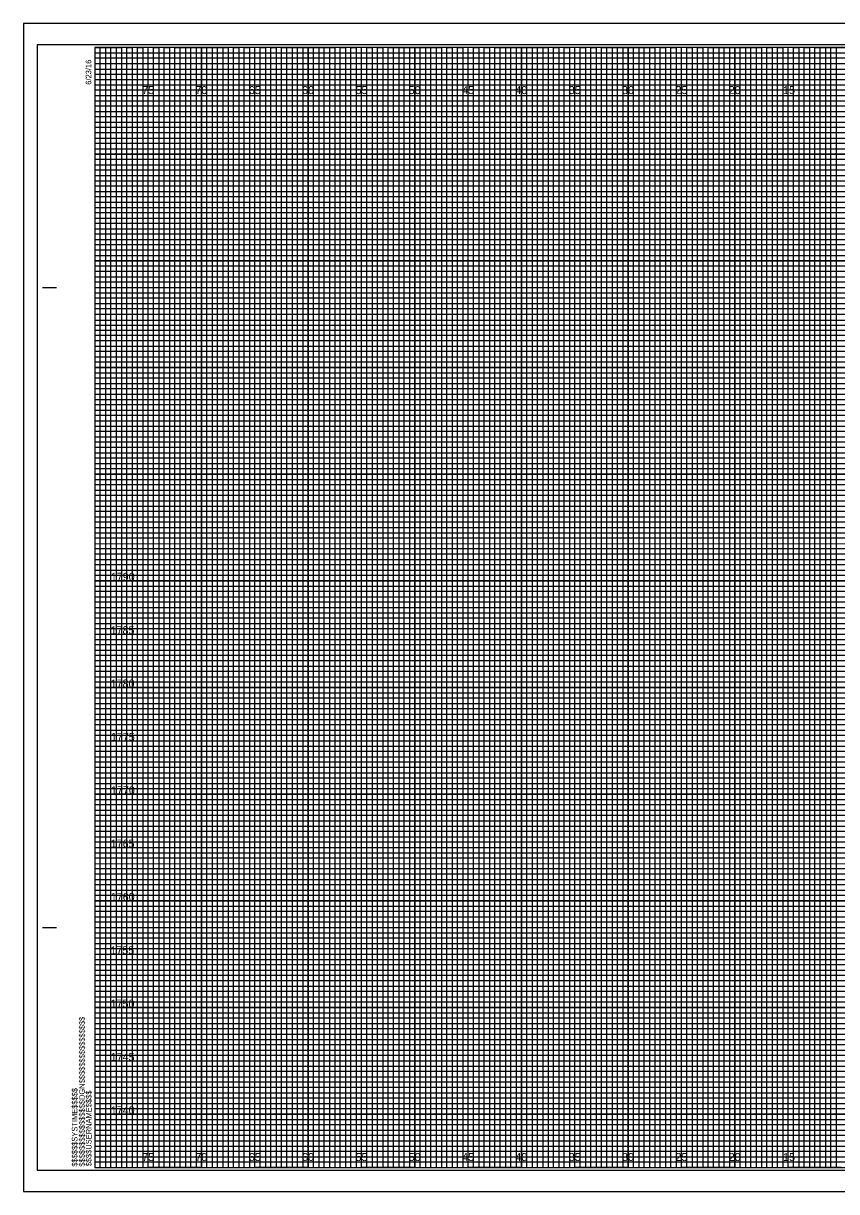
# Model space of a CAD drawing. Extents: x -7 to 162, y -2 to 217.
# Drawn here: x -6.7 to 69.5, y 107.7 to 217.2 of the extents above; entities that cross this region are included whole.
import ezdxf

# ---------------------------------------------------------------- set-up
doc = ezdxf.new("R2010")
doc.units = 0
for name, color, linetype in [('Raster_Level_0', 7, 'Continuous'), ('Scratch_Level_3', 7, 'Continuous'), ('Sheet Cross Section CELL', 7, 'Continuous'), ('Sheet Cross Section Grid Major CELL', 7, 'Continuous'), ('Sheet Cross Section Grid Middle CELL', 7, 'Continuous'), ('Sheet Cross Section Grid Minor 1 CELL', 7, 'Continuous'), ('Sheet Cross Section Grid Minor 2 CELL', 7, 'Continuous'), ('Sheet Cutting Line CELL', 7, 'Continuous'), ('Sheet DOT Grid CELL', 7, 'Continuous'), ('Sheet Plot Border Inside CELL', 7, 'Continuous'), ('Sheet Plot Border Outside CELL', 7, 'Continuous')]:
    doc.layers.add(name, color=color, linetype=linetype)

msp = doc.modelspace()

# ---------------------------------------------------------------- linework, layer by layer
at = {"layer": 'Sheet Cross Section CELL'}
for p, q in [((-4.9, 192.5), (-3.65, 192.5)), ((-4.85, 192.5), (-3.6, 192.5)), ((-4.9, 132.5), (-3.65, 132.5)), ((-4.85, 132.5), (-3.6, 132.5)), ((0, 110), (0, 110)), ((0, 110), (0, 110)), ((0, 110), (0, 110)), ((0, 110), (0, 110)), ((0, 110), (0, 110)), ((0, 110), (0, 110)), ((0, 110), (0, 110))]:
    msp.add_line(p, q, dxfattribs=at)
msp.add_lwpolyline([(160, 215), (0, 215), (0, 110), (160, 110)], close=True, dxfattribs=at)
at = {"layer": 'Sheet Cross Section Grid Major CELL'}
for p, q in [((5, 215), (0, 215)), ((5, 110), (5, 215)), ((15, 215), (10, 215)), ((10, 215), (10, 110)), ((15, 110), (15, 215)), ((25, 215), (20, 215)), ((20, 215), (20, 110)), ((25, 110), (25, 215)), ((35, 215), (30, 215)), ((30, 215), (30, 110)), ((35, 110), (35, 215)), ((45, 215), (40, 215)), ((40, 215), (40, 110)), ((45, 110), (45, 215)), ((55, 215), (50, 215)), ((50, 215), (50, 110)), ((55, 110), (55, 215)), ((65, 215), (60, 215)), ((60, 215), (60, 110)), ((65, 110), (65, 215)), ((10, 110), (5, 110)), ((20, 110), (15, 110)), ((30, 110), (25, 110)), ((40, 110), (35, 110)), ((50, 110), (45, 110)), ((60, 110), (55, 110)), ((70, 110), (65, 110))]:
    msp.add_line(p, q, dxfattribs=at)
for points in [[(0, 210), (160, 210), (160, 205), (0, 205)], [(0, 200), (160, 200), (160, 195), (0, 195)], [(0, 190), (160, 190), (160, 185), (0, 185)], [(0, 180), (160, 180), (160, 175), (0, 175)], [(0, 170), (160, 170), (160, 165), (0, 165)], [(0, 160), (160, 160), (160, 155), (0, 155)], [(0, 150), (160, 150), (160, 145), (0, 145)], [(0, 140), (160, 140), (160, 135), (0, 135)], [(0, 130), (160, 130), (160, 125), (0, 125)], [(0, 120), (160, 120), (160, 115), (0, 115)]]:
    msp.add_lwpolyline(points, dxfattribs=at)
at = {"layer": 'Sheet Cross Section Grid Middle CELL'}
for points in [[(0, 215), (2.5, 215), (2.5, 110), (7.5, 110), (7.5, 215), (12.5, 215), (12.5, 110), (17.5, 110), (17.5, 215), (22.5, 215), (22.5, 110), (27.5, 110), (27.5, 215), (32.5, 215), (32.5, 110), (37.5, 110), (37.5, 215), (42.5, 215), (42.5, 110), (47.5, 110), (47.5, 215), (52.5, 215), (52.5, 110), (57.5, 110), (57.5, 215), (62.5, 215), (62.5, 110), (67.5, 110), (67.5, 215), (72.5, 215)], [(0, 212.5), (137.5, 212.5)], [(0, 202.5), (160, 202.5), (160, 207.5), (0, 207.5)], [(0, 192.5), (160, 192.5), (160, 197.5), (0, 197.5)], [(0, 182.5), (160, 182.5), (160, 187.5), (0, 187.5)], [(0, 172.5), (160, 172.5), (160, 177.5), (0, 177.5)], [(0, 162.5), (160, 162.5), (160, 167.5), (0, 167.5)], [(0, 152.5), (160, 152.5), (160, 157.5), (0, 157.5)], [(0, 142.5), (160, 142.5), (160, 147.5), (0, 147.5)], [(0, 132.5), (160, 132.5), (160, 137.5), (0, 137.5)], [(0, 122.5), (160, 122.5), (160, 127.5), (0, 127.5)], [(0, 112.5), (160, 112.5), (160, 117.5), (0, 117.5)]]:
    msp.add_lwpolyline(points, dxfattribs=at)
at = {"layer": 'Sheet Cross Section Grid Minor 1 CELL'}
for p, q in [((0, 214.5), (130, 214.5)), ((130, 213.99), (0, 213.99)), ((0, 213.99), (0, 213.5)), ((0, 213.5), (130, 213.5)), ((130, 212.94), (0, 212.94)), ((0, 212.94), (0, 212)), ((0, 212), (160, 212))]:
    msp.add_line(p, q, dxfattribs=at)
for points in [[(0, 211.5), (135, 211.5), (160, 211.5), (160, 211), (0, 211)], [(0, 210.5), (160, 210.5), (160, 209.5), (0, 209.5)], [(0, 209), (160, 209), (160, 208.5), (0, 208.49)], [(0, 208), (160, 208), (160, 207), (0, 207)], [(0, 206.5), (160, 206.5), (160, 206), (0, 206)], [(0, 205.5), (160, 205.5), (160, 204.5), (0, 204.5)], [(0, 204), (160, 204), (160, 203.5), (0, 203.5)], [(0, 203), (160, 203), (160, 202), (0, 202)], [(0, 201.5), (160, 201.5), (160, 201), (0, 201)], [(0, 200.5), (160, 200.5), (160, 199.5), (0, 199.5)], [(0, 199), (160, 199), (160, 198.5), (0, 198.5)], [(0, 198), (160, 198), (160, 196.97), (160, 196.5), (160, 196), (0, 196)], [(0, 197), (160, 197), (160, 196.5), (0, 196.5)], [(0, 195.5), (160, 195.5), (160, 194.5), (0, 194.52)], [(0, 194.52), (160, 194.5), (160, 194), (0, 194)], [(0, 193.5), (160, 193.5), (160, 193), (0, 193)], [(0, 192), (160, 192), (160, 191.5), (0, 191.5)], [(0, 191), (160, 191), (160, 190.5), (0, 190.5)], [(-0.04, 189.44), (160, 189.44), (160, 188.94), (-0.04, 188.94)], [(0, 188.5), (160, 188.5), (160, 188), (0, 188)], [(0, 187), (160, 187), (160, 186.5), (0, 186.5)], [(0, 186), (160, 186), (160, 185.5), (0, 185.5)], [(0, 184.5), (160, 184.5), (160, 184), (0, 184)], [(0, 183.5), (160, 183.5), (160, 183), (0, 183)], [(0, 182), (160, 182), (160, 181.5), (0, 181.5)], [(0, 181), (160, 181), (160, 180.5), (0, 180.5)], [(0, 179.5), (160, 179.5), (160, 178.99), (0, 179)], [(0, 178.5), (160, 178.5), (160, 178), (0, 178)], [(0, 177), (160, 177), (160, 176.5), (0, 176.5)], [(0, 176), (160, 176), (160, 175.5), (0, 175.5)], [(0, 174.5), (160, 174.5), (160, 174), (0, 174)], [(0, 173.5), (160, 173.5), (160, 173), (0, 173)], [(0, 172), (160, 172), (160, 171.5), (0, 171.5)], [(0, 171), (160, 171), (160, 170.5), (0, 170.5)], [(0, 169.5), (160, 169.5), (160, 169), (0, 169)], [(0, 168.5), (160.03, 168.46), (160, 168), (0, 168)], [(0, 167), (160, 167), (160, 166.5), (0, 166.5)], [(0, 166), (160, 166), (160, 165.5), (0, 165.5)], [(0, 164.5), (160, 164.5), (160, 164), (0, 164)], [(0, 163.5), (160, 163.5), (160, 163), (0, 163)], [(0, 162), (160, 162), (160, 161.5), (0, 161.5)], [(0, 161), (160, 161), (160, 160.5), (0, 160.5)], [(0, 159.5), (160, 159.5), (160, 159), (0, 159)], [(0, 158.5), (160, 158.5), (160, 158), (0, 158)], [(0, 157), (160, 157), (160, 156.5), (0, 156.5)], [(0, 156), (160, 156), (160, 155.5), (0, 155.5)], [(0, 154.5), (160, 154.5), (160, 154), (0, 154)], [(0, 153.5), (160, 153.5), (160, 153), (0, 153)], [(0, 152), (160, 152), (160, 151.5), (0, 151.5)], [(0, 151), (160, 151), (160, 150.5), (0, 150.5)], [(0, 149.5), (160, 149.5), (160, 148.99), (0, 149)], [(0, 148.5), (160, 148.5), (160, 148), (0, 148)], [(0, 147), (160, 147), (160, 146.5), (0, 146.5)], [(0, 146), (160, 146), (160, 145.5), (0, 145.5)], [(0, 144.5), (160, 144.5), (160, 144), (0, 144)], [(0, 143.5), (160, 143.5), (160, 143), (0, 143)], [(0, 142), (160, 142), (160, 141.5), (0, 141.5)], [(0, 141), (160, 141), (160, 140.5), (0, 140.5)], [(0, 139.5), (160, 139.5), (160, 139), (0, 139)], [(0, 138.5), (160.03, 138.46), (160, 138), (0, 138)], [(0, 137), (160, 137), (160, 136.5), (0, 136.5)], [(0, 136), (160, 136), (160, 135.5), (0, 135.5)], [(0, 134.5), (160, 134.5), (160, 134), (0, 134)], [(0, 133.5), (160, 133.5), (160, 133), (0, 133)], [(0, 132), (160, 132), (160, 131.5), (0, 131.5)], [(0, 131), (160, 131), (160, 130.5), (0, 130.5)], [(0, 129.5), (160, 129.5), (160, 129), (0, 129)], [(0, 128.5), (160, 128.5), (160, 128), (0, 128)], [(0, 127), (160, 127), (160, 126.5), (0, 126.5)], [(0, 126), (160, 126), (160, 125.5), (0, 125.5)], [(0, 124.5), (160, 124.5), (160, 124), (0, 124)], [(0, 123.5), (160, 123.5), (160, 123), (0, 123)], [(0, 122), (160, 122), (160, 121.5), (0, 121.5)], [(0, 121), (160, 121), (160, 120.5), (0, 120.5)], [(0, 119.5), (160, 119.5), (160, 119), (0, 119)], [(0, 118.5), (160, 118.5), (160, 118), (0, 118)], [(0, 117), (160, 117), (160, 116.5), (0, 116.5)], [(0, 116), (160, 116), (160, 115.5), (0, 115.5)], [(0, 114.5), (160, 114.5), (160, 114), (0, 114)], [(0, 113.5), (160, 113.5), (160, 113), (0, 113)], [(0, 112), (160, 112), (160, 111.5), (0, 111.5)], [(0, 111), (160, 111), (160, 110.5), (0, 110.5)]]:
    msp.add_lwpolyline(points, dxfattribs=at)
at = {"layer": 'Sheet Cross Section Grid Minor 2 CELL'}
for points in [[(0, 110), (0.5, 110), (0.5, 215), (1, 215), (1, 110)], [(1, 110), (1.5, 110), (1.5, 215), (2, 215), (2, 110)], [(2.5, 110), (3, 110), (3, 215), (3.5, 215), (3.5, 110)], [(3.5, 110), (4, 110), (4, 215), (4.5, 215), (4.5, 110)], [(5, 110), (5.5, 110), (5.5, 215), (6, 215), (6, 110)], [(6, 110), (6.5, 110), (6.5, 215), (7, 215), (7, 110)], [(7.5, 110), (8, 110), (8, 215), (8.5, 215), (8.5, 110)], [(8.5, 110), (9, 110), (9, 215), (9.5, 215), (9.5, 110)], [(10, 110), (10.5, 110), (10.5, 215), (11, 215), (11, 110)], [(11, 110), (11.5, 110), (11.5, 215), (12, 215), (12, 110)], [(12.5, 110), (13, 110), (13, 215), (13.5, 215), (13.5, 110)], [(13.5, 110), (14, 110), (14, 215), (14.5, 215), (14.5, 110)], [(15, 110), (15.5, 110), (15.5, 215), (16, 215), (16, 110)], [(16, 110), (16.5, 110), (16.5, 215), (17, 215), (17, 110)], [(17.5, 110), (18, 110), (18, 215), (18.5, 215), (18.5, 110)], [(18.5, 110), (19, 110), (19, 215), (19.5, 215), (19.5, 110)], [(20, 110), (20.5, 110), (20.5, 215), (21, 215), (21, 110)], [(21, 110), (21.5, 110), (21.5, 215), (22, 215), (22, 110)], [(22.5, 110), (23, 110), (23, 215), (23.5, 215), (23.5, 110)], [(23.5, 110), (24, 110), (24, 215), (24.5, 215), (24.5, 110)], [(25, 110), (25.5, 110), (25.5, 215), (26, 215), (26, 110)], [(26, 110), (26.5, 110), (26.5, 215), (27, 215), (27, 110)], [(27.5, 110), (28, 110), (28, 215), (28.5, 215), (28.5, 110)], [(28.5, 110), (29, 110), (29, 215), (29.5, 215), (29.5, 110)], [(30, 110), (30.5, 110), (30.5, 215), (31, 215), (31, 110)], [(31, 110), (31.5, 110), (31.5, 215), (32, 215), (32, 110)], [(32.5, 110), (33, 110), (33, 215), (33.5, 215), (33.5, 110)], [(33.5, 110), (34, 110), (34, 215), (34.5, 215), (34.5, 110)], [(35, 110), (35.5, 110), (35.5, 215), (36, 215), (36, 110)], [(36, 110), (36.5, 110), (36.5, 215), (37, 215), (37, 110)], [(37.5, 110), (38, 110), (38, 215), (38.5, 215), (38.5, 110)], [(38.5, 110), (39, 110), (39, 215), (39.5, 215), (39.5, 110)], [(40, 110), (40.5, 110), (40.5, 215), (41, 215), (41, 110)], [(41, 110), (41.5, 110), (41.5, 215), (42, 215), (42, 110)], [(42.5, 110), (43, 110), (43, 215), (43.5, 215), (43.5, 110)], [(43.5, 110), (44, 110), (44, 215), (44.5, 215), (44.5, 110)], [(45, 110), (45.5, 110), (45.5, 215), (46, 215), (46, 110)], [(46, 110), (46.5, 110), (46.5, 215), (47, 215), (47, 110)], [(47.5, 110), (48, 110), (48, 215), (48.5, 215), (48.5, 110)], [(48.5, 110), (49, 110), (49, 215), (49.5, 215), (49.5, 110)], [(50, 110), (50.5, 110), (50.5, 215), (51, 215), (51, 110)], [(51, 110), (51.5, 110), (51.5, 215), (52, 215), (52, 110)], [(52.5, 110), (53, 110), (53, 215), (53.5, 215), (53.5, 110)], [(53.5, 110), (54, 110), (54, 215), (54.5, 215), (54.5, 110)], [(55, 110), (55.5, 110), (55.5, 215), (56, 215), (56, 110)], [(56, 110), (56.5, 110), (56.5, 215), (57, 215), (57, 110)], [(57.5, 110), (58, 110), (58, 215), (58.5, 215), (58.5, 110)], [(58.5, 110), (59, 110), (59, 215), (59.5, 215), (59.5, 110)], [(60, 110), (60.5, 110), (60.5, 215), (61, 215), (61, 110)], [(61, 110), (61.5, 110), (61.5, 215), (62, 215), (62, 110)], [(62.5, 110), (63, 110), (63, 215), (63.5, 215), (63.5, 110)], [(63.5, 110), (64, 110), (64, 215), (64.5, 215), (64.5, 110)], [(65, 110), (65.5, 110), (65.5, 215), (66, 215), (66, 110)], [(66, 110), (66.5, 110), (66.5, 215), (67, 215), (67, 110)], [(67.5, 110), (68, 110), (68, 215), (68.5, 215), (68.5, 110)], [(68.5, 110), (69, 110), (69, 215), (69.5, 215), (69.5, 110)]]:
    msp.add_lwpolyline(points, dxfattribs=at)
at = {"layer": 'Sheet Cutting Line CELL'}
for p, q in [((161.65, 217.25), (-6.7, 217.25)), ((-6.7, 217.25), (-6.7, 107.75)), ((-6.7, 107.75), (161.65, 107.75))]:
    msp.add_line(p, q, dxfattribs=at)
at = {"layer": 'Sheet DOT Grid CELL'}
for p, q in [((5, 110), (5, 215)), ((10, 110), (10, 215)), ((15, 110), (15, 215)), ((20, 110), (20, 215)), ((25, 110), (25, 215)), ((30, 110), (30, 215)), ((35, 110), (35, 215)), ((40, 110), (40, 215)), ((45, 110), (45, 215)), ((50, 110), (50, 215)), ((55, 110), (55, 215)), ((60, 110), (60, 215)), ((65, 110), (65, 215)), ((0, 210), (160, 210)), ((0, 205), (160, 205)), ((0, 200), (160, 200)), ((0, 195), (160, 195)), ((0, 190), (160, 190)), ((0, 185), (160, 185)), ((0, 180), (160, 180)), ((0, 175), (160, 175)), ((0, 170), (160, 170)), ((0, 165), (160, 165)), ((0, 160), (160, 160)), ((0, 155), (160, 155)), ((0, 150), (160, 150)), ((0, 145), (160, 145)), ((0, 140), (160, 140)), ((0, 135), (160, 135)), ((0, 130), (160, 130)), ((0, 125), (160, 125)), ((0, 120), (160, 120)), ((0, 115), (160, 115))]:
    msp.add_line(p, q, dxfattribs=at)
at = {"layer": 'Sheet Plot Border Inside CELL'}
msp.add_lwpolyline([(-5.4, 109.75), (161.2, 109.75), (161.2, 215.25), (-5.4, 215.25)], close=True, dxfattribs=at)
at = {"layer": 'Sheet Plot Border Outside CELL'}
msp.add_lwpolyline([(-6.7, 107.75), (161.65, 107.75), (161.65, 217.25), (-6.7, 217.25)], close=True, dxfattribs=at)

# ---------------------------------------------------------------- texts
at = {"layer": 'Raster_Level_0'}
for s, p in [('75', (4.44, 210.62)), ('70', (9.43, 210.62)), ('65', (14.44, 210.62)), ('60', (19.43, 210.62)), ('55', (24.44, 210.62)), ('50', (29.43, 210.62)), ('45', (34.44, 210.62)), ('40', (39.43, 210.62)), ('35', (44.44, 210.62)), ('30', (49.43, 210.62)), ('25', (54.44, 210.62)), ('20', (59.43, 210.62)), ('15', (64.53, 210.62)), ('75', (4.44, 110.62)), ('70', (9.43, 110.62)), ('65', (14.44, 110.62)), ('60', (19.43, 110.62)), ('55', (24.44, 110.62)), ('50', (29.43, 110.62)), ('45', (34.44, 110.62)), ('40', (39.43, 110.62)), ('35', (44.44, 110.62)), ('30', (49.43, 110.62)), ('25', (54.44, 110.62)), ('20', (59.43, 110.62)), ('15', (64.53, 110.62))]:
    msp.add_text(s, height=0.75, dxfattribs=at).set_placement(p)
at = {"layer": 'Scratch_Level_3'}
for s, p in [('1790', (1.5, 165)), ('1785', (1.48, 160)), ('1780', (1.49, 155)), ('1775', (1.51, 150)), ('1770', (1.52, 145)), ('1765', (1.49, 140)), ('1760', (1.5, 135)), ('1755', (1.47, 130)), ('1750', (1.48, 125)), ('1745', (1.49, 120)), ('1740', (1.5, 115))]:
    msp.add_text(s, height=0.75, dxfattribs=at).set_placement(p)
at = {"layer": 'Sheet Cross Section CELL'}
for s, p in [('6/23/16', (-0.33, 211.5)), ('$$$$$$$$$$$$$$$$DGN$$$$$$$$$$$$$$$$', (-0.94, 110.09)), ('$$$$$$SYSTIME$$$$$', (-1.63, 110.09)), ('$$$$USERNAME$$$$', (-0.31, 110.12))]:
    msp.add_text(s, height=0.525, rotation=90, dxfattribs=at).set_placement(p)

doc.saveas('drawing.dxf')
